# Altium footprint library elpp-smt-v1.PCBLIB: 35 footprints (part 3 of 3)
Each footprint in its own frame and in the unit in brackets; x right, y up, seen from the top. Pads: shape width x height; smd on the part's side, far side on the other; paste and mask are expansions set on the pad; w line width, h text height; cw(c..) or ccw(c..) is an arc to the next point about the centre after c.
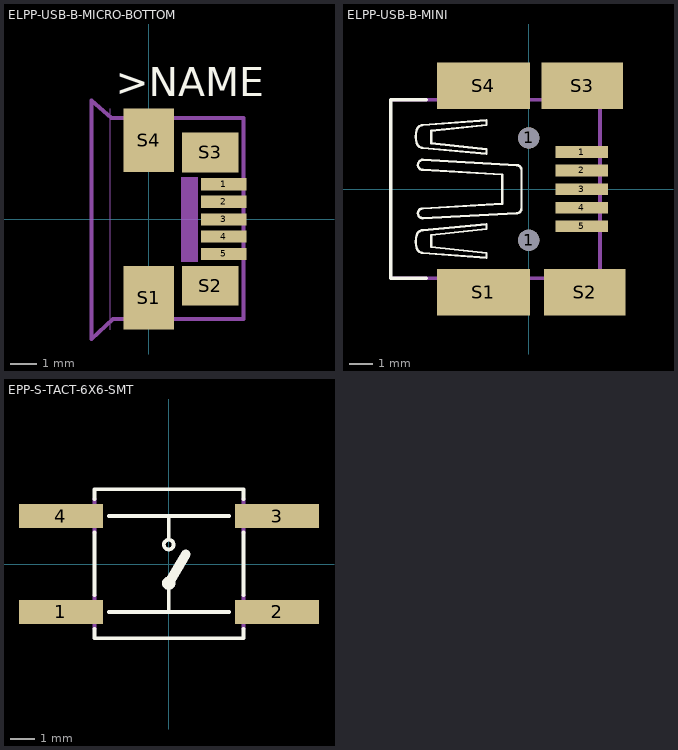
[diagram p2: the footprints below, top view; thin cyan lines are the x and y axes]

## ELPP-USB-B-MICRO-BOTTOM [mil]
pads (9):
  rect 67x18 smd: 1(111,52) 2(111,26) 3(111,0) 4(111,-25.59) 5(111,-51.18)
  rect 75x94 smd: S1(0,-116.14) S4(0,117)
  rect 83x59 smd: S2(91,-98.43) S3(91,99)
Top Overlay:
  text ">NAME" at -49.21,182 h42.5
Top Solder:
  rectangle: -41.34,8 42,54
  rectangle: -41.34,-53.15 42,-7.87
Mechanical 4:
  text ">VALUE" at -55.12,-228.35 h42.5
Mechanical 8:
  rectangle: 48,-62.99 73,63
Mechanical 16:
  lines w0: -57.09,-163.39 -57.09,164
  lines w6: -84.65,-177.17 -53.15,-147.64 140,-147.64 140,150 -55.12,150 -84.65,176 -84.65,-177.17

## ELPP-USB-B-MINI [mil]
pads (11):
  round 36 hole 36: 1(0,-86.61) 1(0,87)
  rect 89x20 smd: 1(90,63) 2(90,32) 3(90,0) 4(90,-31.5) 5(90,-62.99)
  rect 158x79 smd: S1(-76.77,-175.2) S4(-76.77,176)
  rect 138x79 smd: S2(95,-175.2) S3(91,176)
Top Overlay:
  lines w4: -234.25,-151.47 -234.25,-151.24 -233,-151.24 ; -188.04,41 cw(c-179.45,41.41) -179.86,50 -20.44,41 cw(c-20.81,32.44) -12.27,33 -12.27,-32.69 cw(c-20.92,-32.22) -20.44,-40.87 -179.86,-49.04 cw(c-179.86,-40.87) -188.04,-40.87 cw(c-179.86,-40.87) -179.86,-32.69 -44.97,-24.52 -44.97,25 -179.86,33 cw(c-179.95,41.09) -188.04,41 ; -188.04,41 -188.04,41 ; -190.08,-100.14 ccw(c-178.98,-96.74) -179.86,-108.31 -71.54,-116.49 -71.54,-108.31 -165.56,-98.1 -165.56,-77.66 -71.54,-67.44 -71.54,-59.26 -179.86,-69.48 ccw(c-178.98,-81.06) -190.08,-77.66 ccw(c-153.42,-88.9) -190.08,-100.14 ; -190.08,78 cw(c-152.58,89.5) -190.08,101 cw(c-179.11,97.52) -179.86,109 -71.54,117 -71.54,109 -165.56,99 -165.56,78 -71.54,68 -71.54,60 -179.86,70 cw(c-179.11,81.48) -190.08,78
  lines w6: -173.8,-151.24 -234.25,-151.24 -234.25,152 -173.81,152
Mechanical 2:
  text ">NAME" at -175,225 h42.5
Mechanical 4:
  text ">VALUE" at -175,-275 h42.5
Mechanical 16:
  lines w4: -234.25,-151.24 -116.14,-151.24 -116.14,-192.11 -97.42,-192.11 -97.42,-175.76 -53.21,-175.76 -53.21,-192.11 -37.4,-192.11 -37.4,-151.24 ; -234.25,152 -116.14,152 -116.14,193 -99.39,193 -99.39,176 -53.21,176 -53.21,193 -37.4,193 -37.4,152 ; -63.11,-151.46 43,-151.46 ; 62,-152.97 62,-192.11 77,-192.11 77,-175.76 105,-175.76 105,-192.11 121,-192.11 121,-151.65 ; 62,153 62,193 77,193 77,176 105,176 105,193 121,193 121,152
  lines w6: -233.18,-151.47 121,-151.47 121,149 ; -233.18,152 121,152 ; -61.11,152 39,152

## EPP-S-TACT-6X6-SMT [mil]
pads (4):
  rect 138x40 smd: 1(-177.17,-78.74) 2(178,-78.74) 3(178,79) 4(-177.17,79)
Top Overlay:
  circle w6: c0,32 r8
  circle w6: c0,-31.5 r8
  lines w6: -122.05,-106.3 -122.05,-122.05 123,-122.05 123,-106.3 ; -122.05,-51.18 -122.05,52 ; -122.05,107 -122.05,123 123,123 123,107 ; -98.43,-78.74 0,-78.74 ; -98.43,79 0,79 ; 0,-31.5 0,-78.74 ; 0,40 0,79 ; 99,-78.74 0,-78.74 ; 99,79 0,79 ; 123,-51.18 123,52
  lines w16: 0,-31.5 28,16
Mechanical 2:
  text ">NAME" at -118.11,138 h42.5
Mechanical 4:
  text ">VALUE" at -122.05,-185.04 h42.5
Mechanical 16:
  lines w6: -122.05,-106.3 -122.05,-51.18 ; -122.05,52 -122.05,107 ; 123,-106.3 123,-51.18 ; 123,52 123,107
